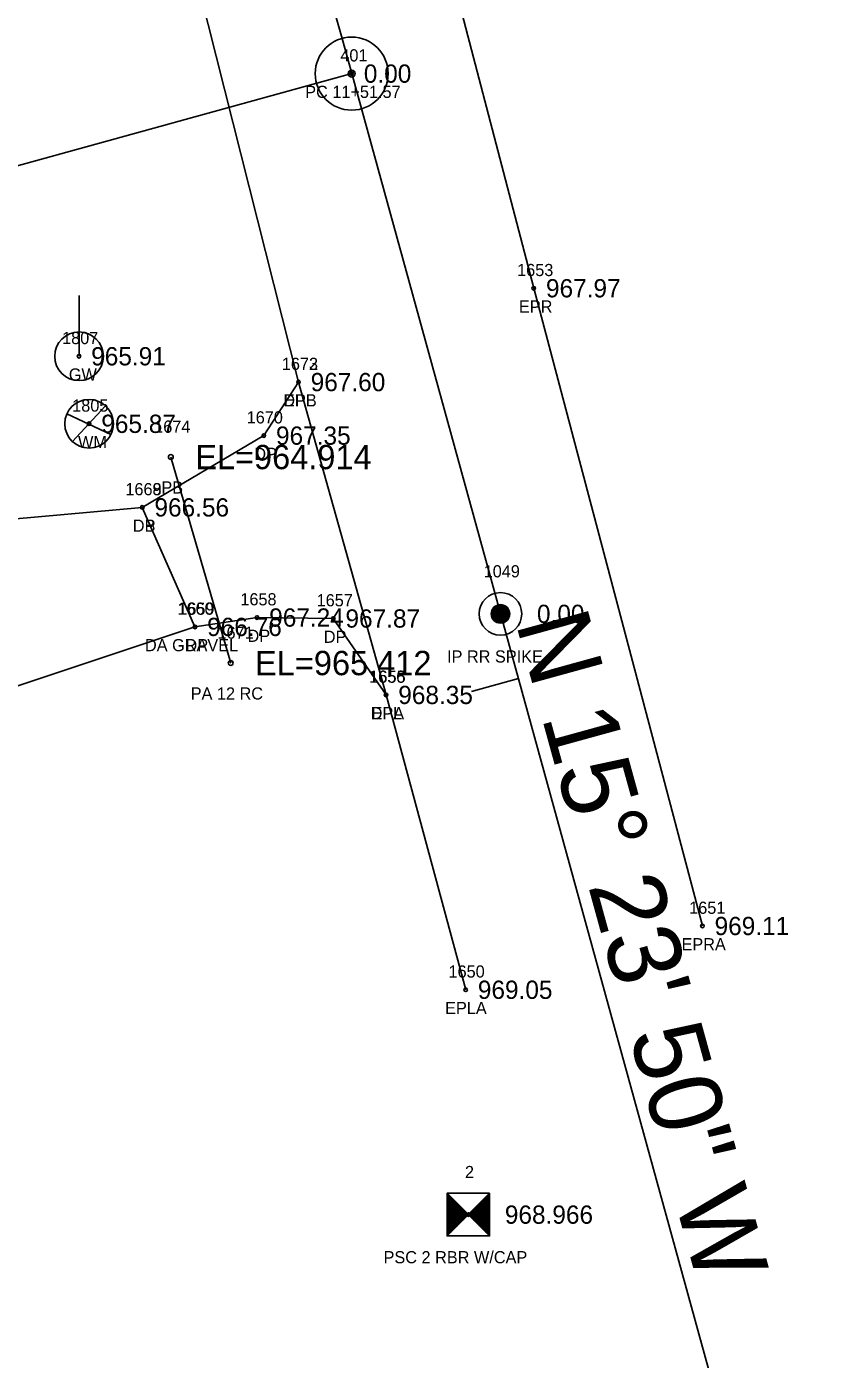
# Model space of a CAD drawing. Extents: x 1528109 to 1531398, y 1157799 to 1162548.
# Drawn here: x 1530649.3 to 1530716.3, y 1158561.9 to 1158671.4 of the extents above; entities that cross this region are included whole.
import ezdxf

# ---------------------------------------------------------------- set-up
doc = ezdxf.new("R2010")
doc.units = 0
for name, color, linetype in [('RD_EX_DR_Pipe', 7, 'Continuous'), ('RD_EX_DR_Pipe_txCode', 7, 'Continuous'), ('RD_EX_Driveway', 7, 'Continuous'), ('RD_EX_Driveway_txCode', 7, 'Continuous'), ('RD_EX_DV_Prop_txCode', 7, 'Continuous'), ('RD_EX_DV_PropPin', 7, 'Continuous'), ('RD_EX_Road', 7, 'Continuous'), ('RD_EX_Road_txCode', 7, 'Continuous'), ('RD_EX_TX_Driveway_ELEV', 7, 'Continuous'), ('RD_EX_TX_DV_Prop_ELEV', 7, 'Continuous'), ('RD_EX_TX_Road_ELEV', 7, 'Continuous'), ('RD_EX_TX_UT_ELEV', 7, 'Continuous'), ('RD_EX_UT', 7, 'Continuous'), ('RD_EX_UT_txCode', 7, 'Continuous'), ('RD_HC_Cl', 7, 'Continuous'), ('RD_HC_Data', 7, 'Continuous'), ('RD_HC_Data_Tic', 7, 'Continuous'), ('RD_HC_Survey', 7, 'Continuous'), ('RD_HC_Survey_ELEV', 7, 'Continuous'), ('RD_HC_txCode', 7, 'Continuous'), ('RD_SMD_Locator', 7, 'Continuous'), ('RD_TX_Pipe_ElevEX', 7, 'Continuous')]:
    doc.layers.add(name, color=color, linetype=linetype)

msp = doc.modelspace()

# ---------------------------------------------------------------- linework, layer by layer
at = {"layer": 'RD_EX_DR_Pipe'}
msp.add_line((1530666.1, 1158619.08), (1530661.18, 1158636.01), dxfattribs=at)
at = {"layer": 'RD_EX_Driveway'}
for points in [[(1530584.5, 1158614.52), (1530618.2, 1158622.19), (1530609.54, 1158656.58), (1530627.63, 1158661.83), (1530637.72, 1158629.96), (1530658.83, 1158631.87)], [(1530678.87, 1158616.46), (1530674.53, 1158622.74), (1530668.26, 1158622.82), (1530663.16, 1158622.05), (1530658.83, 1158631.87), (1530668.82, 1158637.77), (1530671.67, 1158642.17)], [(1530663.16, 1158622.05), (1530626.2, 1158609.76), (1530588.29, 1158600.33)]]:
    msp.add_lwpolyline(points, dxfattribs=at)
at = {"layer": 'RD_EX_DV_PropPin'}
for p, q in [((1530687.54, 1158622.92), (1530687.54, 1158623.31)), ((1530687.57, 1158622.82), (1530687.57, 1158623.41)), ((1530687.61, 1158622.75), (1530687.61, 1158623.49)), ((1530687.64, 1158622.69), (1530687.64, 1158623.54)), ((1530687.68, 1158622.64), (1530687.68, 1158623.59)), ((1530687.71, 1158622.6), (1530687.71, 1158623.63)), ((1530687.75, 1158622.57), (1530687.75, 1158623.67)), ((1530687.78, 1158622.53), (1530687.78, 1158623.7)), ((1530687.82, 1158622.51), (1530687.82, 1158623.73)), ((1530687.85, 1158622.48), (1530687.85, 1158623.75)), ((1530687.89, 1158622.46), (1530687.89, 1158623.77)), ((1530687.92, 1158622.44), (1530687.92, 1158623.79)), ((1530687.96, 1158622.42), (1530687.96, 1158623.81)), ((1530687.99, 1158622.41), (1530687.99, 1158623.82)), ((1530688.03, 1158622.4), (1530688.03, 1158623.84)), ((1530688.06, 1158622.38), (1530688.06, 1158623.85)), ((1530688.1, 1158622.38), (1530688.1, 1158623.86)), ((1530688.13, 1158622.37), (1530688.13, 1158623.86)), ((1530688.17, 1158622.36), (1530688.17, 1158623.87)), ((1530688.2, 1158622.36), (1530688.2, 1158623.87)), ((1530688.24, 1158622.36), (1530688.24, 1158623.88)), ((1530688.27, 1158622.35), (1530688.27, 1158623.88)), ((1530688.31, 1158622.36), (1530688.31, 1158623.88)), ((1530688.34, 1158622.36), (1530688.34, 1158623.87)), ((1530688.38, 1158622.36), (1530688.38, 1158623.87)), ((1530688.41, 1158622.37), (1530688.41, 1158623.86)), ((1530688.45, 1158622.38), (1530688.45, 1158623.86)), ((1530688.48, 1158622.38), (1530688.48, 1158623.85)), ((1530688.52, 1158622.4), (1530688.52, 1158623.84)), ((1530688.55, 1158622.41), (1530688.55, 1158623.82)), ((1530688.59, 1158622.42), (1530688.59, 1158623.81)), ((1530688.62, 1158622.44), (1530688.62, 1158623.79)), ((1530688.66, 1158622.46), (1530688.66, 1158623.77)), ((1530688.69, 1158622.48), (1530688.69, 1158623.75)), ((1530688.73, 1158622.51), (1530688.73, 1158623.73)), ((1530688.76, 1158622.53), (1530688.76, 1158623.7)), ((1530688.8, 1158622.57), (1530688.8, 1158623.67)), ((1530688.83, 1158622.6), (1530688.83, 1158623.63)), ((1530688.87, 1158622.64), (1530688.87, 1158623.59)), ((1530688.9, 1158622.69), (1530688.9, 1158623.54)), ((1530688.94, 1158622.75), (1530688.94, 1158623.49)), ((1530688.97, 1158622.82), (1530688.97, 1158623.41)), ((1530689.01, 1158622.92), (1530689.01, 1158623.31))]:
    msp.add_line(p, q, dxfattribs=at)
for radius in [1.75, 0.761]:
    msp.add_circle((1530688.27, 1158623.12), radius, dxfattribs=at)
at = {"layer": 'RD_EX_Road'}
for points in [[(1530704.87, 1158597.47), (1530691.01, 1158649.88), (1530681.22, 1158687.32), (1530670.59, 1158725), (1530654.42, 1158774.07), (1530635.35, 1158823.15), (1530627.8, 1158842.3), (1530617.35, 1158868.69), (1530597.91, 1158918.04), (1530578.53, 1158967.57), (1530556.7, 1159015.66), (1530524.51, 1159062.45), (1530499.94, 1159086.31), (1530481.93, 1159100.12), (1530434.53, 1159127), (1530416.95, 1159134.13), (1530380.01, 1159145.61), (1530337.52, 1159156.44)], [(1530685.41, 1158592.23), (1530678.87, 1158616.46), (1530671.67, 1158642.17), (1530661.52, 1158682.33), (1530651.17, 1158718.79), (1530644.65, 1158739.35), (1530638.95, 1158757.58), (1530635.45, 1158767.4), (1530616.88, 1158814.94), (1530597.61, 1158862.78), (1530579.09, 1158910.21), (1530559.73, 1158959.38), (1530538.76, 1159006.16), (1530508.96, 1159048.3), (1530469.44, 1159083.44), (1530424.03, 1159108.51), (1530374.97, 1159125.76), (1530332.28, 1159136.67)]]:
    msp.add_lwpolyline(points, dxfattribs=at)
at = {"layer": 'RD_EX_UT'}
for p, q in [((1530653.63, 1158644.29), (1530653.63, 1158649.29)), ((1530652.62, 1158639.57), (1530656.25, 1158637.86)), ((1530653.1, 1158637.28), (1530655.77, 1158640.18))]:
    msp.add_line(p, q, dxfattribs=at)
for centre in [(1530653.63, 1158644.29), (1530654.46, 1158638.74)]:
    msp.add_circle(centre, 2, dxfattribs=at)
at = {"layer": 'RD_HC_Cl'}
msp.add_line((1530716.29, 1158521.39), (1530676.04, 1158667.52), dxfattribs=at)
msp.add_arc((1528952, 1158192.73), 1788.23, 15.39728, 21.95502, dxfattribs=at)
at = {"layer": 'RD_HC_Data'}
msp.add_line((1530676.04, 1158667.52), (1530563.31, 1158636.47), dxfattribs=at)
for radius in [3, 0.282]:
    msp.add_circle((1530676.04, 1158667.52), radius, dxfattribs=at)
at = {"layer": 'RD_HC_Data_Tic'}
msp.add_line((1530689.74, 1158617.8), (1530685.88, 1158616.74), dxfattribs=at)
at = {"layer": 'RD_HC_Survey'}
for p, q in [((1530683.88, 1158575.5), (1530687.38, 1158572)), ((1530687.38, 1158575.5), (1530683.88, 1158572)), ((1530683.9, 1158575.47), (1530683.9, 1158572.02)), ((1530683.93, 1158575.45), (1530683.93, 1158572.05)), ((1530683.95, 1158575.42), (1530683.95, 1158572.07)), ((1530683.98, 1158575.4), (1530683.98, 1158572.1)), ((1530684, 1158575.37), (1530684, 1158572.12)), ((1530684.03, 1158575.35), (1530684.03, 1158572.15)), ((1530684.05, 1158575.32), (1530684.05, 1158572.17)), ((1530684.08, 1158575.3), (1530684.08, 1158572.2)), ((1530684.1, 1158575.27), (1530684.1, 1158572.22)), ((1530684.13, 1158575.25), (1530684.13, 1158572.24)), ((1530684.15, 1158575.22), (1530684.15, 1158572.27)), ((1530684.18, 1158575.2), (1530684.18, 1158572.29)), ((1530684.2, 1158575.18), (1530684.2, 1158572.32)), ((1530684.23, 1158575.15), (1530684.23, 1158572.34)), ((1530684.25, 1158575.13), (1530684.25, 1158572.37)), ((1530684.28, 1158575.1), (1530684.28, 1158572.39)), ((1530684.3, 1158575.08), (1530684.3, 1158572.42)), ((1530684.33, 1158575.05), (1530684.33, 1158572.44)), ((1530684.35, 1158575.03), (1530684.35, 1158572.47)), ((1530684.38, 1158575), (1530684.38, 1158572.49)), ((1530684.4, 1158574.98), (1530684.4, 1158572.52)), ((1530684.42, 1158574.95), (1530684.42, 1158572.54)), ((1530684.45, 1158574.93), (1530684.45, 1158572.57)), ((1530684.47, 1158574.9), (1530684.47, 1158572.59)), ((1530684.5, 1158574.88), (1530684.5, 1158572.62)), ((1530684.52, 1158574.85), (1530684.52, 1158572.64)), ((1530684.55, 1158574.83), (1530684.55, 1158572.67)), ((1530684.57, 1158574.8), (1530684.57, 1158572.69)), ((1530684.6, 1158574.78), (1530684.6, 1158572.71)), ((1530684.62, 1158574.75), (1530684.62, 1158572.74)), ((1530684.65, 1158574.73), (1530684.65, 1158572.76)), ((1530684.67, 1158574.71), (1530684.67, 1158572.79)), ((1530686.59, 1158574.71), (1530686.59, 1158572.79)), ((1530686.61, 1158574.73), (1530686.61, 1158572.76)), ((1530686.64, 1158574.75), (1530686.64, 1158572.74)), ((1530686.66, 1158574.78), (1530686.66, 1158572.71)), ((1530686.69, 1158574.8), (1530686.69, 1158572.69)), ((1530686.71, 1158574.83), (1530686.71, 1158572.67)), ((1530686.74, 1158574.85), (1530686.74, 1158572.64)), ((1530686.76, 1158574.88), (1530686.76, 1158572.62)), ((1530686.79, 1158574.9), (1530686.79, 1158572.59)), ((1530686.81, 1158574.93), (1530686.81, 1158572.57)), ((1530686.84, 1158574.95), (1530686.84, 1158572.54)), ((1530686.86, 1158574.98), (1530686.86, 1158572.52)), ((1530686.89, 1158575), (1530686.89, 1158572.49)), ((1530686.91, 1158575.03), (1530686.91, 1158572.47)), ((1530686.93, 1158575.05), (1530686.93, 1158572.44)), ((1530686.96, 1158575.08), (1530686.96, 1158572.42)), ((1530686.98, 1158575.1), (1530686.98, 1158572.39)), ((1530687.01, 1158575.13), (1530687.01, 1158572.37)), ((1530687.03, 1158575.15), (1530687.03, 1158572.34)), ((1530687.06, 1158575.18), (1530687.06, 1158572.32)), ((1530687.08, 1158575.2), (1530687.08, 1158572.29)), ((1530687.11, 1158575.22), (1530687.11, 1158572.27)), ((1530687.13, 1158575.25), (1530687.13, 1158572.24)), ((1530687.16, 1158575.27), (1530687.16, 1158572.22)), ((1530687.18, 1158575.3), (1530687.18, 1158572.2)), ((1530687.21, 1158575.32), (1530687.21, 1158572.17)), ((1530687.23, 1158575.35), (1530687.23, 1158572.15)), ((1530687.26, 1158575.37), (1530687.26, 1158572.12)), ((1530687.28, 1158575.4), (1530687.28, 1158572.1)), ((1530687.31, 1158575.42), (1530687.31, 1158572.07)), ((1530687.33, 1158575.45), (1530687.33, 1158572.05)), ((1530687.36, 1158575.47), (1530687.36, 1158572.02)), ((1530684.7, 1158574.68), (1530684.7, 1158572.81)), ((1530684.72, 1158574.66), (1530684.72, 1158572.84)), ((1530684.75, 1158574.63), (1530684.75, 1158572.86)), ((1530684.77, 1158574.61), (1530684.77, 1158572.89)), ((1530684.8, 1158574.58), (1530684.8, 1158572.91)), ((1530684.82, 1158574.56), (1530684.82, 1158572.94)), ((1530684.85, 1158574.53), (1530684.85, 1158572.96)), ((1530684.87, 1158574.51), (1530684.87, 1158572.99)), ((1530684.89, 1158574.48), (1530684.89, 1158573.01)), ((1530684.92, 1158574.46), (1530684.92, 1158573.04)), ((1530684.94, 1158574.43), (1530684.94, 1158573.06)), ((1530684.97, 1158574.41), (1530684.97, 1158573.09)), ((1530684.99, 1158574.38), (1530684.99, 1158573.11)), ((1530685.02, 1158574.36), (1530685.02, 1158573.14)), ((1530685.04, 1158574.33), (1530685.04, 1158573.16)), ((1530685.07, 1158574.31), (1530685.07, 1158573.19)), ((1530685.09, 1158574.28), (1530685.09, 1158573.21)), ((1530685.12, 1158574.26), (1530685.12, 1158573.23)), ((1530685.14, 1158574.23), (1530685.14, 1158573.26)), ((1530685.17, 1158574.21), (1530685.17, 1158573.28)), ((1530685.19, 1158574.19), (1530685.19, 1158573.31)), ((1530685.22, 1158574.16), (1530685.22, 1158573.33)), ((1530685.24, 1158574.14), (1530685.24, 1158573.36)), ((1530685.27, 1158574.11), (1530685.27, 1158573.38)), ((1530685.29, 1158574.09), (1530685.29, 1158573.41)), ((1530685.32, 1158574.06), (1530685.32, 1158573.43)), ((1530685.34, 1158574.04), (1530685.34, 1158573.46)), ((1530685.37, 1158574.01), (1530685.37, 1158573.48)), ((1530685.39, 1158573.99), (1530685.39, 1158573.51)), ((1530685.41, 1158573.96), (1530685.41, 1158573.53)), ((1530685.44, 1158573.94), (1530685.44, 1158573.56)), ((1530685.46, 1158573.91), (1530685.46, 1158573.58)), ((1530685.49, 1158573.89), (1530685.49, 1158573.61)), ((1530685.51, 1158573.86), (1530685.51, 1158573.63)), ((1530685.54, 1158573.84), (1530685.54, 1158573.66)), ((1530685.56, 1158573.81), (1530685.56, 1158573.68)), ((1530685.59, 1158573.79), (1530685.59, 1158573.7)), ((1530685.61, 1158573.76), (1530685.61, 1158573.73)), ((1530685.65, 1158573.76), (1530685.65, 1158573.73)), ((1530685.67, 1158573.79), (1530685.67, 1158573.7)), ((1530685.7, 1158573.81), (1530685.7, 1158573.68)), ((1530685.72, 1158573.84), (1530685.72, 1158573.66)), ((1530685.75, 1158573.86), (1530685.75, 1158573.63)), ((1530685.77, 1158573.89), (1530685.77, 1158573.61)), ((1530685.8, 1158573.91), (1530685.8, 1158573.58)), ((1530685.82, 1158573.94), (1530685.82, 1158573.56)), ((1530685.85, 1158573.96), (1530685.85, 1158573.53)), ((1530685.87, 1158573.99), (1530685.87, 1158573.51)), ((1530685.9, 1158574.01), (1530685.9, 1158573.48)), ((1530685.92, 1158574.04), (1530685.92, 1158573.46)), ((1530685.94, 1158574.06), (1530685.94, 1158573.43)), ((1530685.97, 1158574.09), (1530685.97, 1158573.41)), ((1530685.99, 1158574.11), (1530685.99, 1158573.38)), ((1530686.02, 1158574.14), (1530686.02, 1158573.36)), ((1530686.04, 1158574.16), (1530686.04, 1158573.33)), ((1530686.07, 1158574.19), (1530686.07, 1158573.31)), ((1530686.09, 1158574.21), (1530686.09, 1158573.28)), ((1530686.12, 1158574.23), (1530686.12, 1158573.26)), ((1530686.14, 1158574.26), (1530686.14, 1158573.23)), ((1530686.17, 1158574.28), (1530686.17, 1158573.21)), ((1530686.19, 1158574.31), (1530686.19, 1158573.19)), ((1530686.22, 1158574.33), (1530686.22, 1158573.16)), ((1530686.24, 1158574.36), (1530686.24, 1158573.14)), ((1530686.27, 1158574.38), (1530686.27, 1158573.11)), ((1530686.29, 1158574.41), (1530686.29, 1158573.09)), ((1530686.32, 1158574.43), (1530686.32, 1158573.06)), ((1530686.34, 1158574.46), (1530686.34, 1158573.04)), ((1530686.37, 1158574.48), (1530686.37, 1158573.01)), ((1530686.39, 1158574.51), (1530686.39, 1158572.99)), ((1530686.41, 1158574.53), (1530686.41, 1158572.96)), ((1530686.44, 1158574.56), (1530686.44, 1158572.94)), ((1530686.46, 1158574.58), (1530686.46, 1158572.91)), ((1530686.49, 1158574.61), (1530686.49, 1158572.89)), ((1530686.51, 1158574.63), (1530686.51, 1158572.86)), ((1530686.54, 1158574.66), (1530686.54, 1158572.84)), ((1530686.56, 1158574.68), (1530686.56, 1158572.81))]:
    msp.add_line(p, q, dxfattribs=at)
msp.add_lwpolyline([(1530687.38, 1158575.5), (1530683.88, 1158575.5), (1530683.88, 1158572), (1530687.38, 1158572)], close=True, dxfattribs=at)
at = {"layer": 'RD_SMD_Locator'}
for centre, radius in [((1530676.04, 1158667.52), 0.15), ((1530691.01, 1158649.88), 0.15), ((1530653.63, 1158644.29), 0.15), ((1530671.67, 1158642.17), 0.15), ((1530671.67, 1158642.17), 0.15), ((1530654.46, 1158638.74), 0.15), ((1530668.82, 1158637.77), 0.15), ((1530661.18, 1158636.01), 0.2), ((1530658.83, 1158631.87), 0.15), ((1530658.83, 1158631.87), 0.15), ((1530668.26, 1158622.82), 0.15), ((1530674.53, 1158622.74), 0.15), ((1530688.27, 1158623.12), 0.15), ((1530663.16, 1158622.05), 0.15), ((1530663.16, 1158622.05), 0.15), ((1530666.1, 1158619.08), 0.2), ((1530678.87, 1158616.46), 0.15), ((1530678.87, 1158616.46), 0.15), ((1530704.87, 1158597.47), 0.15), ((1530685.41, 1158592.23), 0.15), ((1530685.63, 1158573.75), 0.15)]:
    msp.add_circle(centre, radius, dxfattribs=at)

# ---------------------------------------------------------------- texts
at = {"layer": 'RD_EX_DR_Pipe_txCode'}
for s, p in [('1674', (1530659.81, 1158638.01)), ('PB', (1530660.4, 1158633.01)), ('1671', (1530665.01, 1158621.08)), ('PA 12 RC', (1530662.81, 1158616.08))]:
    msp.add_text(s, height=1, dxfattribs=at).set_placement(p)
at = {"layer": 'RD_EX_Driveway_txCode'}
for s, p in [('1672', (1530670.3, 1158643.17)), ('DPB', (1530670.42, 1158640.17)), ('1670', (1530667.41, 1158638.77)), ('DP', (1530668.04, 1158635.77)), ('1668', (1530657.44, 1158632.87)), ('1669', (1530657.44, 1158632.87)), ('DB', (1530658.05, 1158629.87)), ('DP', (1530658.05, 1158629.87)), ('1660', (1530661.72, 1158623.05)), ('1659', (1530661.79, 1158623.05)), ('1658', (1530666.89, 1158623.82)), ('1657', (1530673.16, 1158623.74)), ('DP', (1530667.48, 1158620.82)), ('DA GRAVEL', (1530659.05, 1158620.05)), ('DP', (1530662.38, 1158620.05)), ('DP', (1530673.75, 1158620.74)), ('1656', (1530677.47, 1158617.46)), ('DPA', (1530677.6, 1158614.46))]:
    msp.add_text(s, height=1, dxfattribs=at).set_placement(p)
at = {"layer": 'RD_EX_DV_Prop_txCode'}
for s, p in [('1049', (1530686.89, 1158626.12)), ('IP RR SPIKE', (1530683.88, 1158619.12))]:
    msp.add_text(s, height=1, dxfattribs=at).set_placement(p)
at = {"layer": 'RD_EX_Road_txCode'}
for s, p in [('1653', (1530689.64, 1158650.88)), ('EPR', (1530689.79, 1158647.88)), ('1673', (1530670.3, 1158643.17)), ('EPL', (1530670.47, 1158640.17)), ('1655', (1530677.5, 1158617.46)), ('EPL', (1530677.66, 1158614.46)), ('1651', (1530703.78, 1158598.47)), ('EPRA', (1530703.15, 1158595.47)), ('1650', (1530684, 1158593.23)), ('EPLA', (1530683.72, 1158590.23))]:
    msp.add_text(s, height=1, dxfattribs=at).set_placement(p)
at = {"layer": 'RD_EX_TX_Driveway_ELEV'}
for s, p in [('967.60', (1530672.67, 1158641.42)), ('967.35', (1530669.82, 1158637.02)), ('966.56', (1530659.83, 1158631.12)), ('966.56', (1530659.83, 1158631.12)), ('967.24', (1530669.26, 1158622.07)), ('967.87', (1530675.53, 1158621.99)), ('966.76', (1530664.16, 1158621.3)), ('966.76', (1530664.16, 1158621.3)), ('968.35', (1530679.87, 1158615.71))]:
    msp.add_text(s, height=1.5, dxfattribs=at).set_placement(p)
at = {"layer": 'RD_EX_TX_DV_Prop_ELEV'}
msp.add_text('0.00', height=1.5, dxfattribs=at).set_placement((1530691.27, 1158622.37))
at = {"layer": 'RD_EX_TX_Road_ELEV'}
for s, p in [('967.97', (1530692.01, 1158649.13)), ('967.60', (1530672.67, 1158641.42)), ('968.35', (1530679.87, 1158615.71)), ('969.11', (1530705.87, 1158596.72)), ('969.05', (1530686.41, 1158591.48))]:
    msp.add_text(s, height=1.5, dxfattribs=at).set_placement(p)
at = {"layer": 'RD_EX_TX_UT_ELEV'}
for s, p in [('965.91', (1530654.63, 1158643.54)), ('965.87', (1530655.46, 1158637.99))]:
    msp.add_text(s, height=1.5, dxfattribs=at).set_placement(p)
at = {"layer": 'RD_EX_UT_txCode'}
for s, p in [('1807', (1530652.24, 1158645.29)), ('GW', (1530652.79, 1158642.29)), ('1805', (1530653.07, 1158639.74)), ('WM', (1530653.55, 1158636.74))]:
    msp.add_text(s, height=1, dxfattribs=at).set_placement(p)
at = {"layer": 'RD_HC_Data'}
msp.add_text('N 15%%d 23\' 50" W', height=6, rotation=285.3973, dxfattribs=at).set_placement((1530689.51, 1158622.39))
at = {"layer": 'RD_HC_Survey_ELEV'}
for s, p in [('0.00', (1530677.04, 1158666.77)), ('968.966', (1530688.63, 1158573))]:
    msp.add_text(s, height=1.5, dxfattribs=at).set_placement(p)
at = {"layer": 'RD_HC_txCode'}
for s, p in [('401', (1530675.11, 1158668.52)), ('PC 11+51.57', (1530672.22, 1158665.52)), ('2', (1530685.35, 1158576.75)), ('PSC 2 RBR W/CAP', (1530678.66, 1158569.75))]:
    msp.add_text(s, height=1, dxfattribs=at).set_placement(p)
at = {"layer": 'RD_TX_Pipe_ElevEX'}
for s, p in [('EL=964.914', (1530663.18, 1158635.01)), ('EL=965.412', (1530668.1, 1158618.08))]:
    msp.add_text(s, height=2, dxfattribs=at).set_placement(p)

doc.saveas('drawing.dxf')
